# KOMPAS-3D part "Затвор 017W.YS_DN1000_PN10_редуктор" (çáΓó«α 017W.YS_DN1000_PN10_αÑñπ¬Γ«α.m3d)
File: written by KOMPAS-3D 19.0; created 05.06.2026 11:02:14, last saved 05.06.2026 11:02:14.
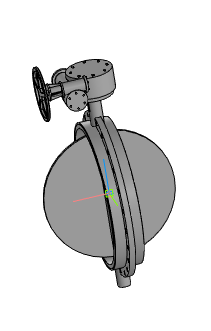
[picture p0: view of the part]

Document properties: Автор: Энергия; Полное имя файла: ..\..\..\3d для проектировщиков\x.x Тип 017W.Y(S) Затвор дисковый поворотный межфланцевый\Затвор 017W.Y(S)_DN50-DN1200_редуктор\Затвор 017W.YS_DN1000_PN10_редуктор.a3d

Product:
- Part/product: Затвор 017W.YS_DN1000_PN10_редуктор
    Масса: 660.73

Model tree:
1. Операция без истории:1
